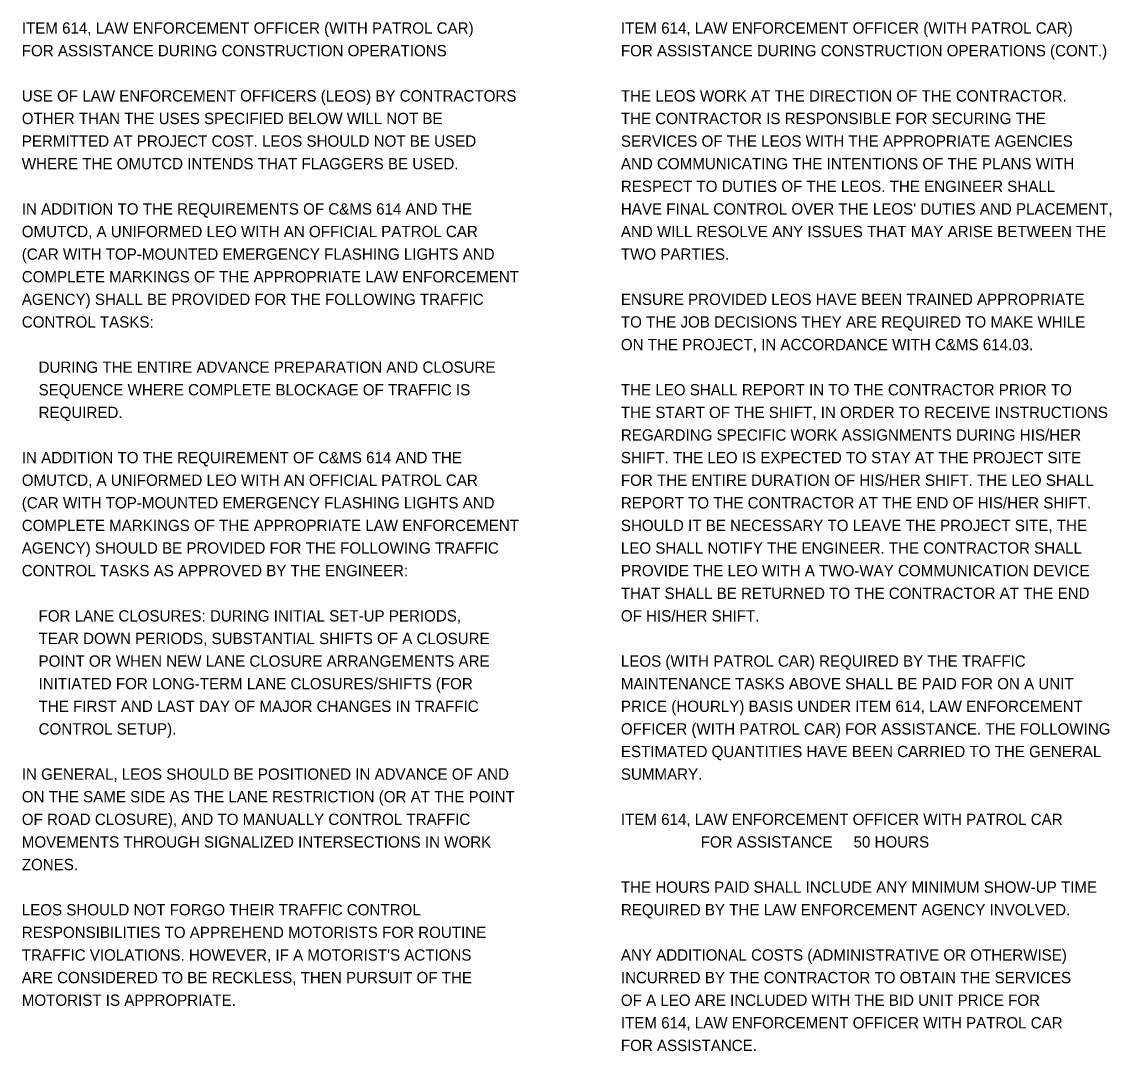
# Model space of a CAD drawing. Extents: x 0 to 1381193, y -3 to 468856.
# Drawn here: x 36.24 to 49.73, y 8.4 to 21.15 of the extents above; entities that cross this region are included whole.
import ezdxf

# ---------------------------------------------------------------- set-up
doc = ezdxf.new("R2010")
doc.units = 0
doc.layers.add('SV_X_Random_Point', color=7, linetype='Continuous')

msp = doc.modelspace()

# ---------------------------------------------------------------- texts
at = {"layer": 'SV_X_Random_Point'}
for s, p in [('ITEM 614, LAW ENFORCEMENT OFFICER (WITH PATROL CAR)', (36.241, 21)), ('ITEM 614, LAW ENFORCEMENT OFFICER (WITH PATROL CAR)', (43.661, 21)), ('FOR ASSISTANCE DURING CONSTRUCTION OPERATIONS', (36.241, 20.72)), ('FOR ASSISTANCE DURING CONSTRUCTION OPERATIONS (CONT.)', (43.661, 20.72)), ('USE OF LAW ENFORCEMENT OFFICERS (LEOS) BY CONTRACTORS', (36.241, 20.16)), ('THE LEOS WORK AT THE DIRECTION OF THE CONTRACTOR.', (43.661, 20.16)), ('OTHER THAN THE USES SPECIFIED BELOW WILL NOT BE', (36.241, 19.88)), ('THE CONTRACTOR IS RESPONSIBLE FOR SECURING THE', (43.661, 19.88)), ('PERMITTED AT PROJECT COST. LEOS SHOULD NOT BE USED', (36.241, 19.6)), ('SERVICES OF THE LEOS WITH THE APPROPRIATE AGENCIES', (43.661, 19.6)), ('WHERE THE OMUTCD INTENDS THAT FLAGGERS BE USED.', (36.241, 19.32)), ('AND COMMUNICATING THE INTENTIONS OF THE PLANS WITH', (43.661, 19.32)), ('RESPECT TO DUTIES OF THE LEOS. THE ENGINEER SHALL', (43.661, 19.04)), ('IN ADDITION TO THE REQUIREMENTS OF C&MS 614 AND THE', (36.241, 18.76)), ("HAVE FINAL CONTROL OVER THE LEOS' DUTIES AND PLACEMENT,", (43.661, 18.76)), ('OMUTCD, A UNIFORMED LEO WITH AN OFFICIAL PATROL CAR', (36.241, 18.48)), ('AND WILL RESOLVE ANY ISSUES THAT MAY ARISE BETWEEN THE', (43.661, 18.48)), ('(CAR WITH TOP-MOUNTED EMERGENCY FLASHING LIGHTS AND', (36.241, 18.2)), ('TWO PARTIES.', (43.661, 18.2)), ('COMPLETE MARKINGS OF THE APPROPRIATE LAW ENFORCEMENT', (36.241, 17.92)), ('AGENCY) SHALL BE PROVIDED FOR THE FOLLOWING TRAFFIC', (36.241, 17.64)), ('ENSURE PROVIDED LEOS HAVE BEEN TRAINED APPROPRIATE', (43.661, 17.64)), ('CONTROL TASKS:', (36.241, 17.36)), ('TO THE JOB DECISIONS THEY ARE REQUIRED TO MAKE WHILE', (43.661, 17.36)), ('ON THE PROJECT, IN ACCORDANCE WITH C&MS 614.03.', (43.661, 17.08)), ('    DURING THE ENTIRE ADVANCE PREPARATION AND CLOSURE', (36.241, 16.8)), ('    SEQUENCE WHERE COMPLETE BLOCKAGE OF TRAFFIC IS', (36.241, 16.52)), ('THE LEO SHALL REPORT IN TO THE CONTRACTOR PRIOR TO', (43.661, 16.52)), ('    REQUIRED.', (36.241, 16.24)), ('THE START OF THE SHIFT, IN ORDER TO RECEIVE INSTRUCTIONS', (43.661, 16.24)), ('REGARDING SPECIFIC WORK ASSIGNMENTS DURING HIS/HER', (43.661, 15.96)), ('IN ADDITION TO THE REQUIREMENT OF C&MS 614 AND THE', (36.241, 15.68)), ('SHIFT. THE LEO IS EXPECTED TO STAY AT THE PROJECT SITE', (43.661, 15.68)), ('OMUTCD, A UNIFORMED LEO WITH AN OFFICIAL PATROL CAR', (36.241, 15.4)), ('FOR THE ENTIRE DURATION OF HIS/HER SHIFT. THE LEO SHALL', (43.661, 15.4)), ('(CAR WITH TOP-MOUNTED EMERGENCY FLASHING LIGHTS AND', (36.241, 15.12)), ('REPORT TO THE CONTRACTOR AT THE END OF HIS/HER SHIFT.', (43.661, 15.12)), ('COMPLETE MARKINGS OF THE APPROPRIATE LAW ENFORCEMENT', (36.241, 14.84)), ('SHOULD IT BE NECESSARY TO LEAVE THE PROJECT SITE, THE', (43.661, 14.84)), ('AGENCY) SHOULD BE PROVIDED FOR THE FOLLOWING TRAFFIC', (36.241, 14.56)), ('LEO SHALL NOTIFY THE ENGINEER. THE CONTRACTOR SHALL', (43.661, 14.56)), ('CONTROL TASKS AS APPROVED BY THE ENGINEER:', (36.241, 14.28)), ('PROVIDE THE LEO WITH A TWO-WAY COMMUNICATION DEVICE', (43.661, 14.28)), ('THAT SHALL BE RETURNED TO THE CONTRACTOR AT THE END', (43.661, 14)), ('    FOR LANE CLOSURES: DURING INITIAL SET-UP PERIODS,', (36.241, 13.72)), ('OF HIS/HER SHIFT.', (43.661, 13.72)), ('    TEAR DOWN PERIODS, SUBSTANTIAL SHIFTS OF A CLOSURE', (36.241, 13.44)), ('    POINT OR WHEN NEW LANE CLOSURE ARRANGEMENTS ARE', (36.241, 13.16)), ('LEOS (WITH PATROL CAR) REQUIRED BY THE TRAFFIC', (43.661, 13.16)), ('    INITIATED FOR LONG-TERM LANE CLOSURES/SHIFTS (FOR', (36.241, 12.88)), ('MAINTENANCE TASKS ABOVE SHALL BE PAID FOR ON A UNIT', (43.661, 12.88)), ('    THE FIRST AND LAST DAY OF MAJOR CHANGES IN TRAFFIC', (36.241, 12.6)), ('PRICE (HOURLY) BASIS UNDER ITEM 614, LAW ENFORCEMENT', (43.661, 12.6)), ('    CONTROL SETUP).', (36.241, 12.32)), ('OFFICER (WITH PATROL CAR) FOR ASSISTANCE. THE FOLLOWING', (43.661, 12.32)), ('ESTIMATED QUANTITIES HAVE BEEN CARRIED TO THE GENERAL', (43.661, 12.04)), ('IN GENERAL, LEOS SHOULD BE POSITIONED IN ADVANCE OF AND', (36.241, 11.76)), ('SUMMARY.', (43.661, 11.76)), ('ON THE SAME SIDE AS THE LANE RESTRICTION (OR AT THE POINT', (36.241, 11.48)), ('OF ROAD CLOSURE), AND TO MANUALLY CONTROL TRAFFIC', (36.241, 11.2)), ('ITEM 614, LAW ENFORCEMENT OFFICER WITH PATROL CAR', (43.661, 11.2)), ('MOVEMENTS THROUGH SIGNALIZED INTERSECTIONS IN WORK', (36.241, 10.92)), ('                   FOR ASSISTANCE     50 HOURS', (43.661, 10.92)), ('ZONES.', (36.241, 10.64)), ('THE HOURS PAID SHALL INCLUDE ANY MINIMUM SHOW-UP TIME', (43.661, 10.36)), ('LEOS SHOULD NOT FORGO THEIR TRAFFIC CONTROL', (36.241, 10.08)), ('REQUIRED BY THE LAW ENFORCEMENT AGENCY INVOLVED.', (43.661, 10.08)), ('RESPONSIBILITIES TO APPREHEND MOTORISTS FOR ROUTINE', (36.241, 9.8)), ("TRAFFIC VIOLATIONS. HOWEVER, IF A MOTORIST'S ACTIONS", (36.241, 9.52)), ('ANY ADDITIONAL COSTS (ADMINISTRATIVE OR OTHERWISE)', (43.661, 9.52)), ('ARE CONSIDERED TO BE RECKLESS, THEN PURSUIT OF THE', (36.241, 9.24)), ('INCURRED BY THE CONTRACTOR TO OBTAIN THE SERVICES', (43.661, 9.24)), ('MOTORIST IS APPROPRIATE.', (36.241, 8.96)), ('OF A LEO ARE INCLUDED WITH THE BID UNIT PRICE FOR', (43.661, 8.96)), ('ITEM 614, LAW ENFORCEMENT OFFICER WITH PATROL CAR', (43.661, 8.68)), ('FOR ASSISTANCE.', (43.661, 8.4))]:
    msp.add_text(s, height=0.14, dxfattribs=at).set_placement(p)

doc.saveas('drawing.dxf')
